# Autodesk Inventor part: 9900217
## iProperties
Author: Charles Bliss
Shininess: 15.0
Angle Display Precision: 2
Document Length Units: 11272
Document Angle Units: 11286
Document Time Units: 11279
Document Mass Units: 11290
Document Length Units Precision: 3
Document Angle Units Precision: 2
Compacted: True
PropertySet Name: _Private Model Information
Created: 2002-03
Part Number: 9900217
Document SubType Name: Modeling
Designer: Charles Bliss
Control State: 0
Master: False
Checked Out: False
PropertySet Name: Design Tracking Control
Density: 0.0
Volumn: 0.0
Area: 0.0
PropertySet Name: Model Information
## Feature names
1. Revolution1
2. Revolution2
3. Fillet2
